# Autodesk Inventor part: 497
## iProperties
Author: Administrator
Shininess: 64.0
Angle Display Precision: 2
Document Length Units: 11272
Document Angle Units: 11286
Document Time Units: 11279
Document Mass Units: 11290
Document Length Units Precision: 3
Document Angle Units Precision: 2
Compacted: True
PropertySet Name: _Private Model Information
Created: 2002-03
Part Number: 497
Material: Stainless Steel, 440C
Document SubType Name: Modeling
Designer: Administrator
Control State: 0
Master: False
Checked Out: False
PropertySet Name: Design Tracking Control
Density: 0.0
Volumn: 0.0
Area: 0.0
PropertySet Name: Model Information
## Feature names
1. Revolution1
